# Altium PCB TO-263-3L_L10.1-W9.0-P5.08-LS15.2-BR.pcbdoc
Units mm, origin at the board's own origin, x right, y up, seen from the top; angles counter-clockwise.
Board outline 29.66 x 23.5 mm, 2 copper layers (Top Layer, Bottom Layer), stack 0 mm thick; 1 components, 0 nets, 3 pads, 0 vias.
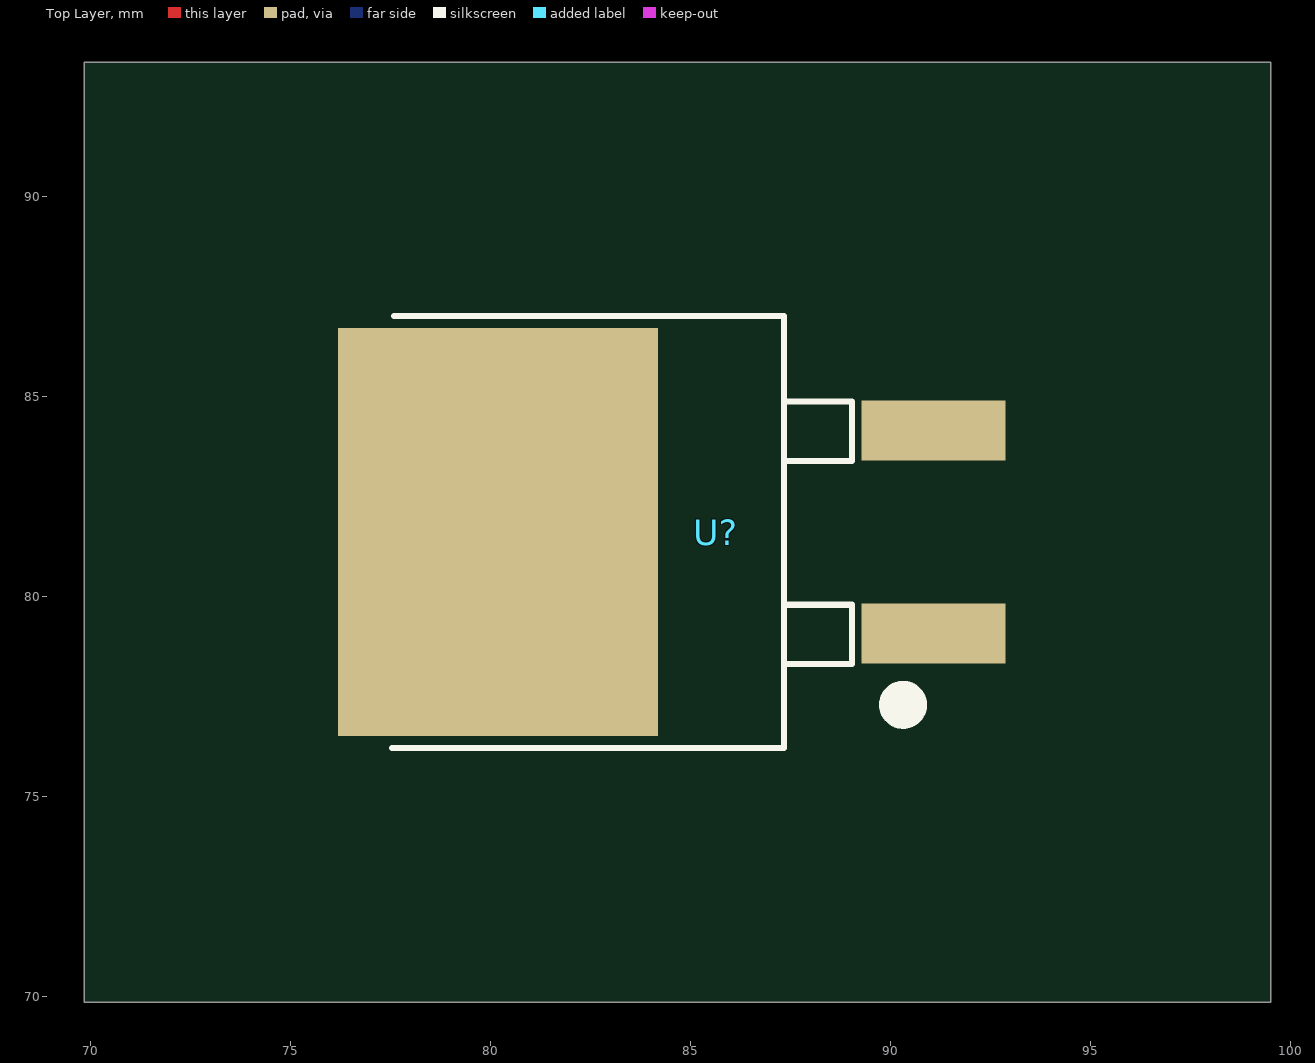
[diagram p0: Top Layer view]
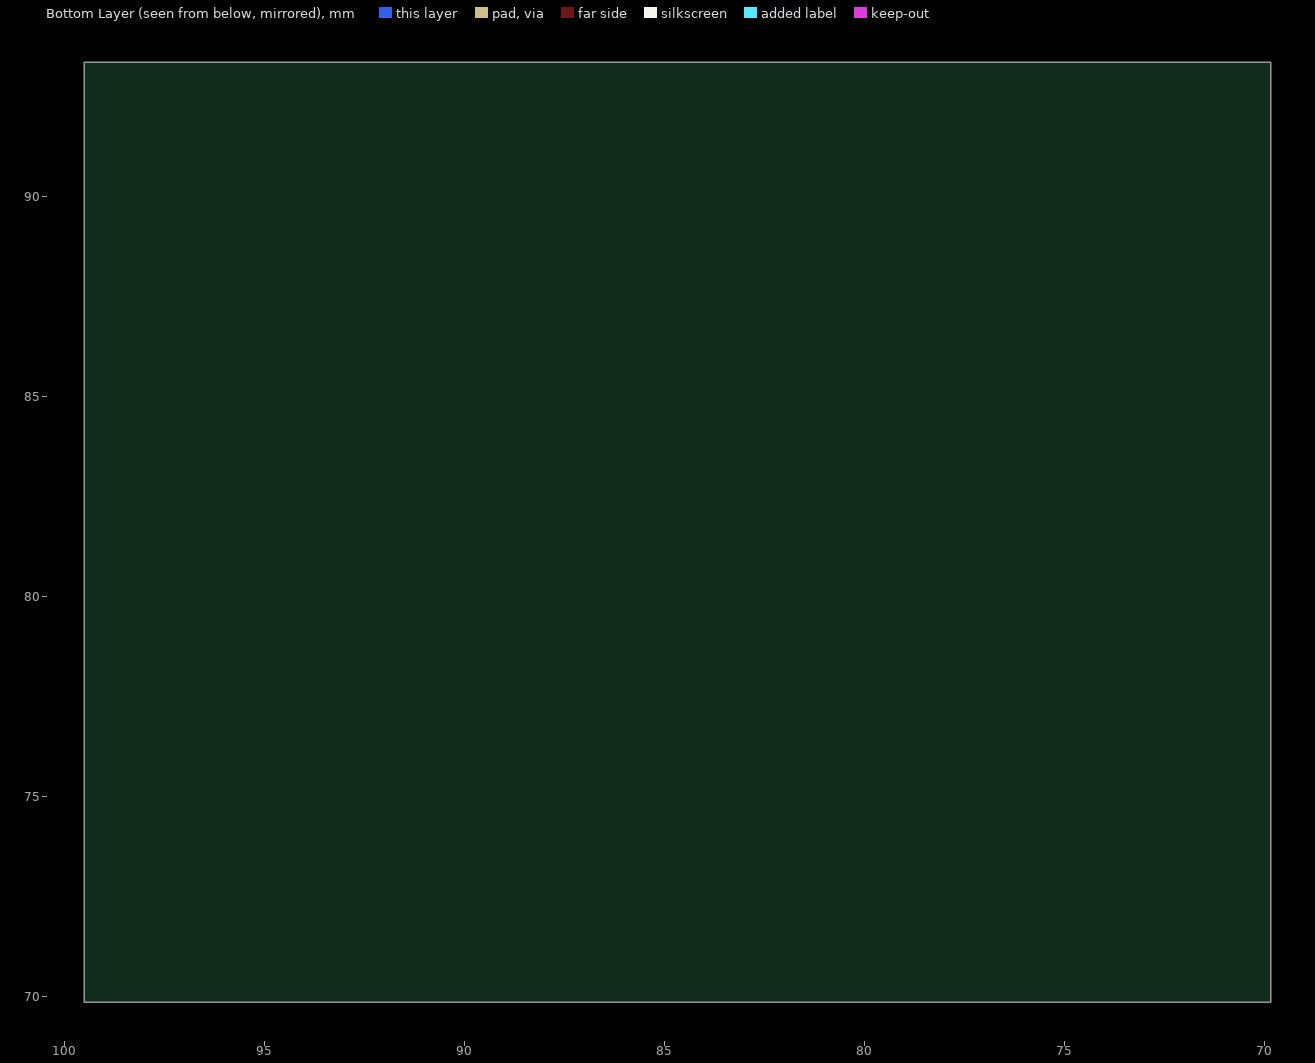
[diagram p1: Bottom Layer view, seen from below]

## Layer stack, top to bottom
Top Layer: signal copper (thickness not stored)
Bottom Layer: signal copper (thickness not stored)

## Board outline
99.512,69.85 69.85,69.85 69.85,93.35 99.512,93.35

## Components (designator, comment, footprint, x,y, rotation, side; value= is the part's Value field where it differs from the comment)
U? "" TO-263-3L_L10.1-W9.0-P5.08-LS15.2-BR 85.642,81.6 r0 top

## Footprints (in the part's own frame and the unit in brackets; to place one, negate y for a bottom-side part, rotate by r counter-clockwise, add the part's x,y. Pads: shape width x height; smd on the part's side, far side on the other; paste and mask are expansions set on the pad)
TO-263-3L_L10.1-W9.0-P5.08-LS15.2-BR [mm]
  rect 3.6x1.5 smd: 1(5.442,-2.54) 2(5.442,2.54)
  rect 8x10.2 smd: 3(-5.442,0)
  silkscreen extent -8.1,-5.4 4.98,5.4

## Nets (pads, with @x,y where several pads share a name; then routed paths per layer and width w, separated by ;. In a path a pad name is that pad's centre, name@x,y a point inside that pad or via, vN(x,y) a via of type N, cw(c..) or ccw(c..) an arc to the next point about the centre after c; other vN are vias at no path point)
pads on no net: U?.1 U?.2 U?.3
